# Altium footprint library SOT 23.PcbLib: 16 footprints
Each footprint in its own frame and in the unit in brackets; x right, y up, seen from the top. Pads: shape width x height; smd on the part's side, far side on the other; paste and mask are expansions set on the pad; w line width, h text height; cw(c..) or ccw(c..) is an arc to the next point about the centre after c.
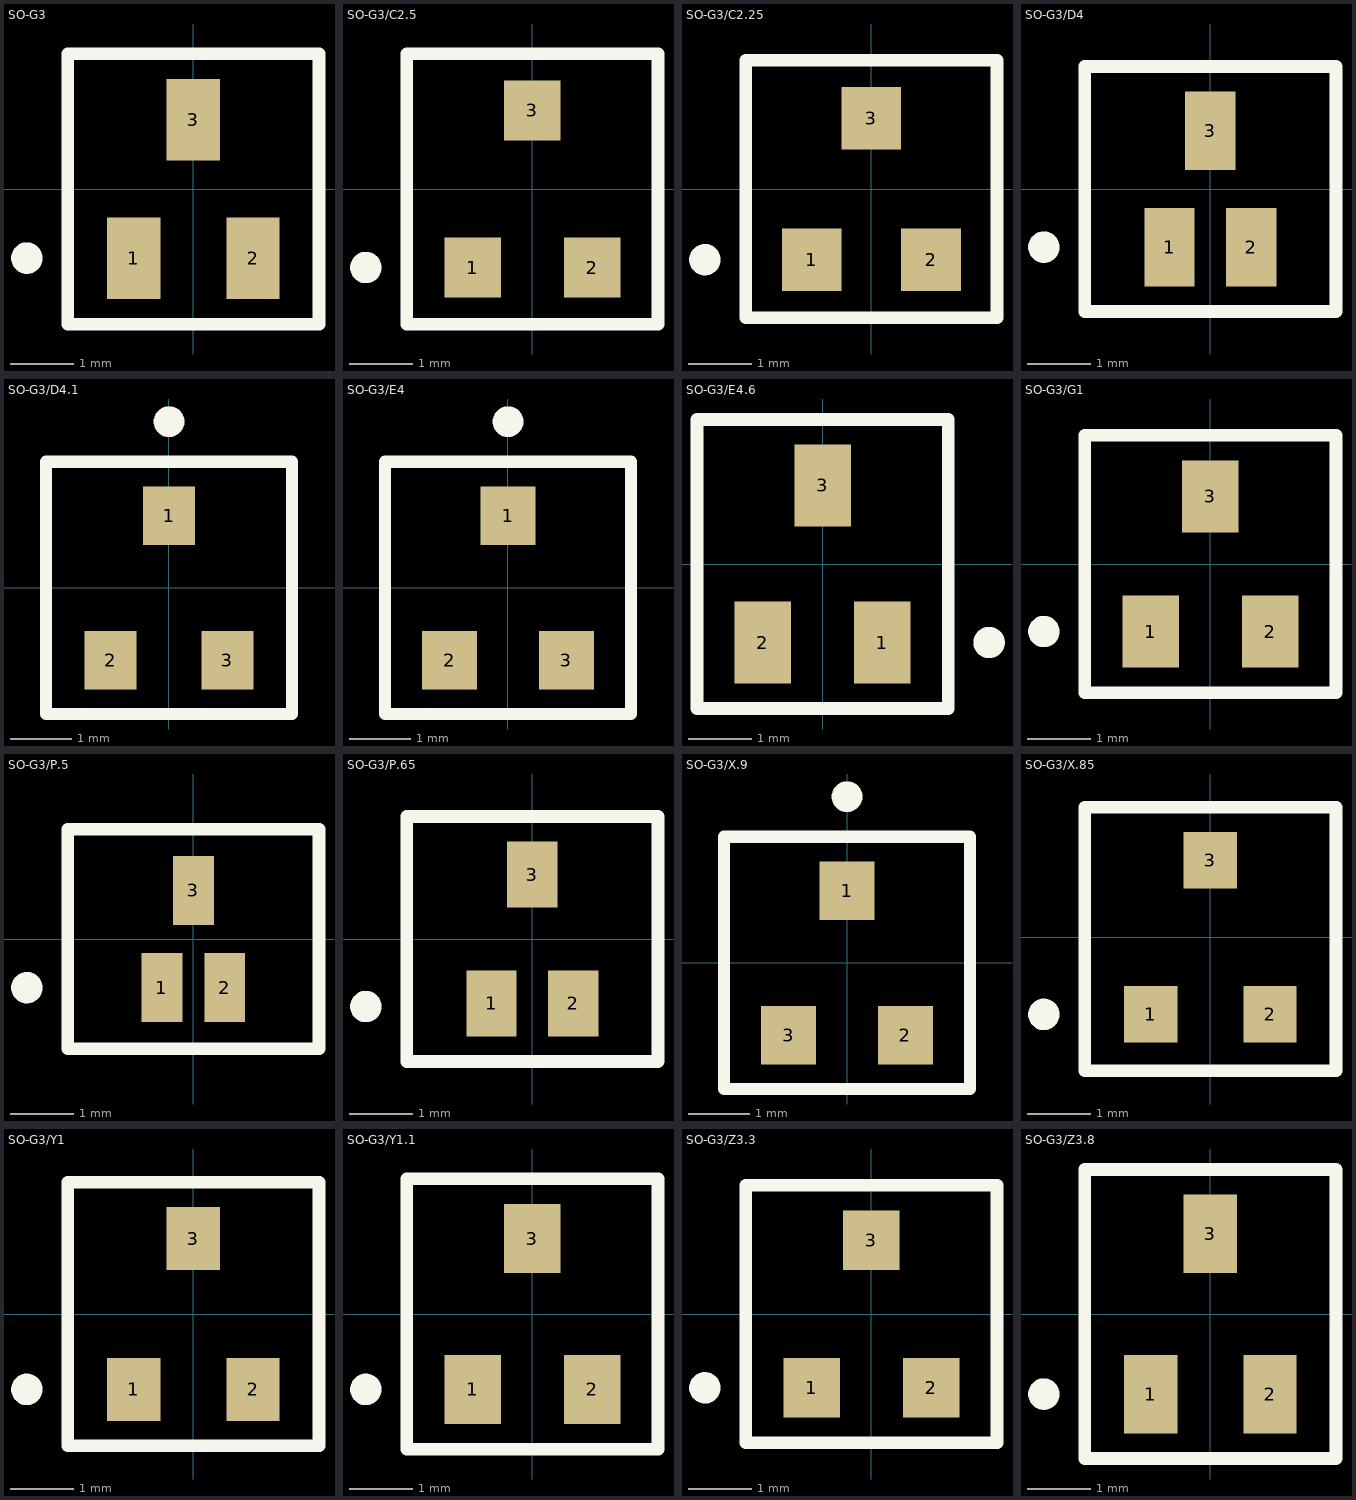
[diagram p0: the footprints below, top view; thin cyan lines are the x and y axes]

## SO-G3 [mm]
pads (3):
  rect 0.85x1.3 smd: 1(-0.95,-1.1) 2(0.95,-1.1) 3(0,1.1)
Top Overlay:
  circle w0.25: c-2.65,-1.1 r0.125
  lines w0.2: -2,-2.15 2,-2.15 2,2.15 -2,2.15 -2,-2.15

## SO-G3/C2.5 [mm]
pads (3):
  rect 0.9x0.95 smd: 1(-0.95,-1.25) 2(0.95,-1.25) 3(0,1.25)
Top Overlay:
  circle w0.25: c-2.65,-1.25 r0.125
  lines w0.2: -2,-2.15 2,-2.15 2,2.15 -2,2.15 -2,-2.15

## SO-G3/C2.25 [mm]
pads (3):
  rect 0.95x1 smd: 1(-0.95,-1.125) 2(0.95,-1.125) 3(0,1.125)
Top Overlay:
  circle w0.25: c-2.65,-1.125 r0.125
  lines w0.2: -2,-2.05 -2,2.05 2,2.05 2,-2.05 -2,-2.05

## SO-G3/D4 [mm]
pads (3):
  rect 0.8x1.25 smd: 1(-0.65,-0.925) 2(0.65,-0.925) 3(0,0.925)
Top Overlay:
  circle w0.25: c-2.65,-0.925 r0.125
  lines w0.2: -2,-1.95 2,-1.95 2,1.95 -2,1.95 -2,-1.95

## SO-G3/D4.1 [mm]
pads (3):
  rect 0.85x0.95 smd: 1(0,1.175) 2(-0.95,-1.175) 3(0.95,-1.175)
Top Overlay:
  circle w0.25: c0,2.7 r0.125
  lines w0.2: -2,-2.05 2,-2.05 2,2.05 -2,2.05 -2,-2.05

## SO-G3/E4 [mm]
pads (3):
  rect 0.9x0.95 smd: 1(0,1.175) 2(-0.95,-1.175) 3(0.95,-1.175)
Top Overlay:
  circle w0.25: c0,2.7 r0.125
  lines w0.2: -2,-2.05 -2,2.05 2,2.05 2,-2.05 -2,-2.05

## SO-G3/E4.6 [mm]
pads (3):
  rect 0.9x1.3 smd: 1(0.95,-1.25) 2(-0.95,-1.25) 3(0,1.25)
Top Overlay:
  circle w0.25: c2.65,-1.25 r0.125
  lines w0.2: -2,-2.3 -2,2.3 2,2.3 2,-2.3 -2,-2.3

## SO-G3/G1 [mm]
pads (3):
  rect 0.9x1.15 smd: 1(-0.95,-1.075) 2(0.95,-1.075) 3(0,1.075)
Top Overlay:
  circle w0.25: c-2.65,-1.075 r0.125
  lines w0.2: -2,-2.05 2,-2.05 2,2.05 -2,2.05 -2,-2.05

## SO-G3/P.5 [mm]
pads (3):
  rect 0.65x1.1 smd: 1(-0.5,-0.775) 2(0.5,-0.775) 3(0,0.775)
Top Overlay:
  circle w0.25: c-2.65,-0.775 r0.125
  lines w0.2: -2,-1.75 2,-1.75 2,1.75 -2,1.75 -2,-1.75

## SO-G3/P.65 [mm]
pads (3):
  rect 0.8x1.05 smd: 1(-0.65,-1.025) 2(0.65,-1.025) 3(0,1.025)
Top Overlay:
  circle w0.25: c-2.65,-1.075 r0.125
  lines w0.2: -2,-1.95 -2,1.95 2,1.95 2,-1.95 -2,-1.95

## SO-G3/X.9 [mm]
pads (3):
  rect 0.9x0.95 smd: 1(0,1.175) 2(0.95,-1.175) 3(-0.95,-1.175)
Top Overlay:
  circle w0.25: c0,2.7 r0.125
  lines w0.2: -2,-2.05 -2,2.05 2,2.05 2,-2.05 -2,-2.05

## SO-G3/X.85 [mm]
pads (3):
  rect 0.85x0.9 smd: 1(-0.95,-1.225) 2(0.95,-1.225) 3(0,1.225)
Top Overlay:
  circle w0.25: c-2.65,-1.225 r0.125
  lines w0.2: -2,-2.125 2,-2.125 2,2.075 -2,2.075 -2,-2.125

## SO-G3/Y1 [mm]
pads (3):
  rect 0.85x1 smd: 1(-0.95,-1.2) 2(0.95,-1.2) 3(0,1.2)
Top Overlay:
  circle w0.25: c-2.65,-1.2 r0.125
  lines w0.2: -2,-2.1 2,-2.1 2,2.1 -2,2.1 -2,-2.1

## SO-G3/Y1.1 [mm]
pads (3):
  rect 0.9x1.1 smd: 1(-0.95,-1.2) 2(0.95,-1.2) 3(0,1.2)
Top Overlay:
  circle w0.25: c-2.65,-1.2 r0.125
  lines w0.2: -2,-2.15 2,-2.15 ; -2,-2.1 -2,2.1 ; -2,2.15 2,2.15 ; 2,-2.1 2,2.1

## SO-G3/Z3.3 [mm]
pads (3):
  rect 0.9x0.95 smd: 1(-0.95,-1.175) 2(0.95,-1.175) 3(0,1.175)
Top Overlay:
  circle w0.25: c-2.65,-1.175 r0.125
  lines w0.2: -2,-2.05 2,-2.05 2,2.05 -2,2.05 -2,-2.05

## SO-G3/Z3.8 [mm]
pads (3):
  rect 0.85x1.25 smd: 1(-0.95,-1.275) 2(0.95,-1.275) 3(0,1.275)
Top Overlay:
  circle w0.25: c-2.65,-1.275 r0.125
  lines w0.2: -2,-2.3 -2,2.3 2,2.3 2,-2.3 -2,-2.3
